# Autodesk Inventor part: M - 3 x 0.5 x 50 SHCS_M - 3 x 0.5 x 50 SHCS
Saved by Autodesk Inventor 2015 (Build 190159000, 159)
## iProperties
Created: 2015-01
Part Number: M - 3 x 0.5 x 50 SHCS_M - 3 x 0.5 x 50 SHCS
Material: Steel, Galvanized
Document SubType Name: Modeling
Designer: TODD D MILLER
Mass: 3.2576 g
Surface Area: 5.77712 cm^2
Volume: 0.414981 cm^3
Density: 7.85 g/cm^3
Appearance: Galvanized
Author: TODD D MILLER
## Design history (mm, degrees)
node "M - 3 x 0.5 x 50 SHCS_M - 3 x 0.5 x 50 SHCS.ipt1"
node "Hex"
node "Base1"
